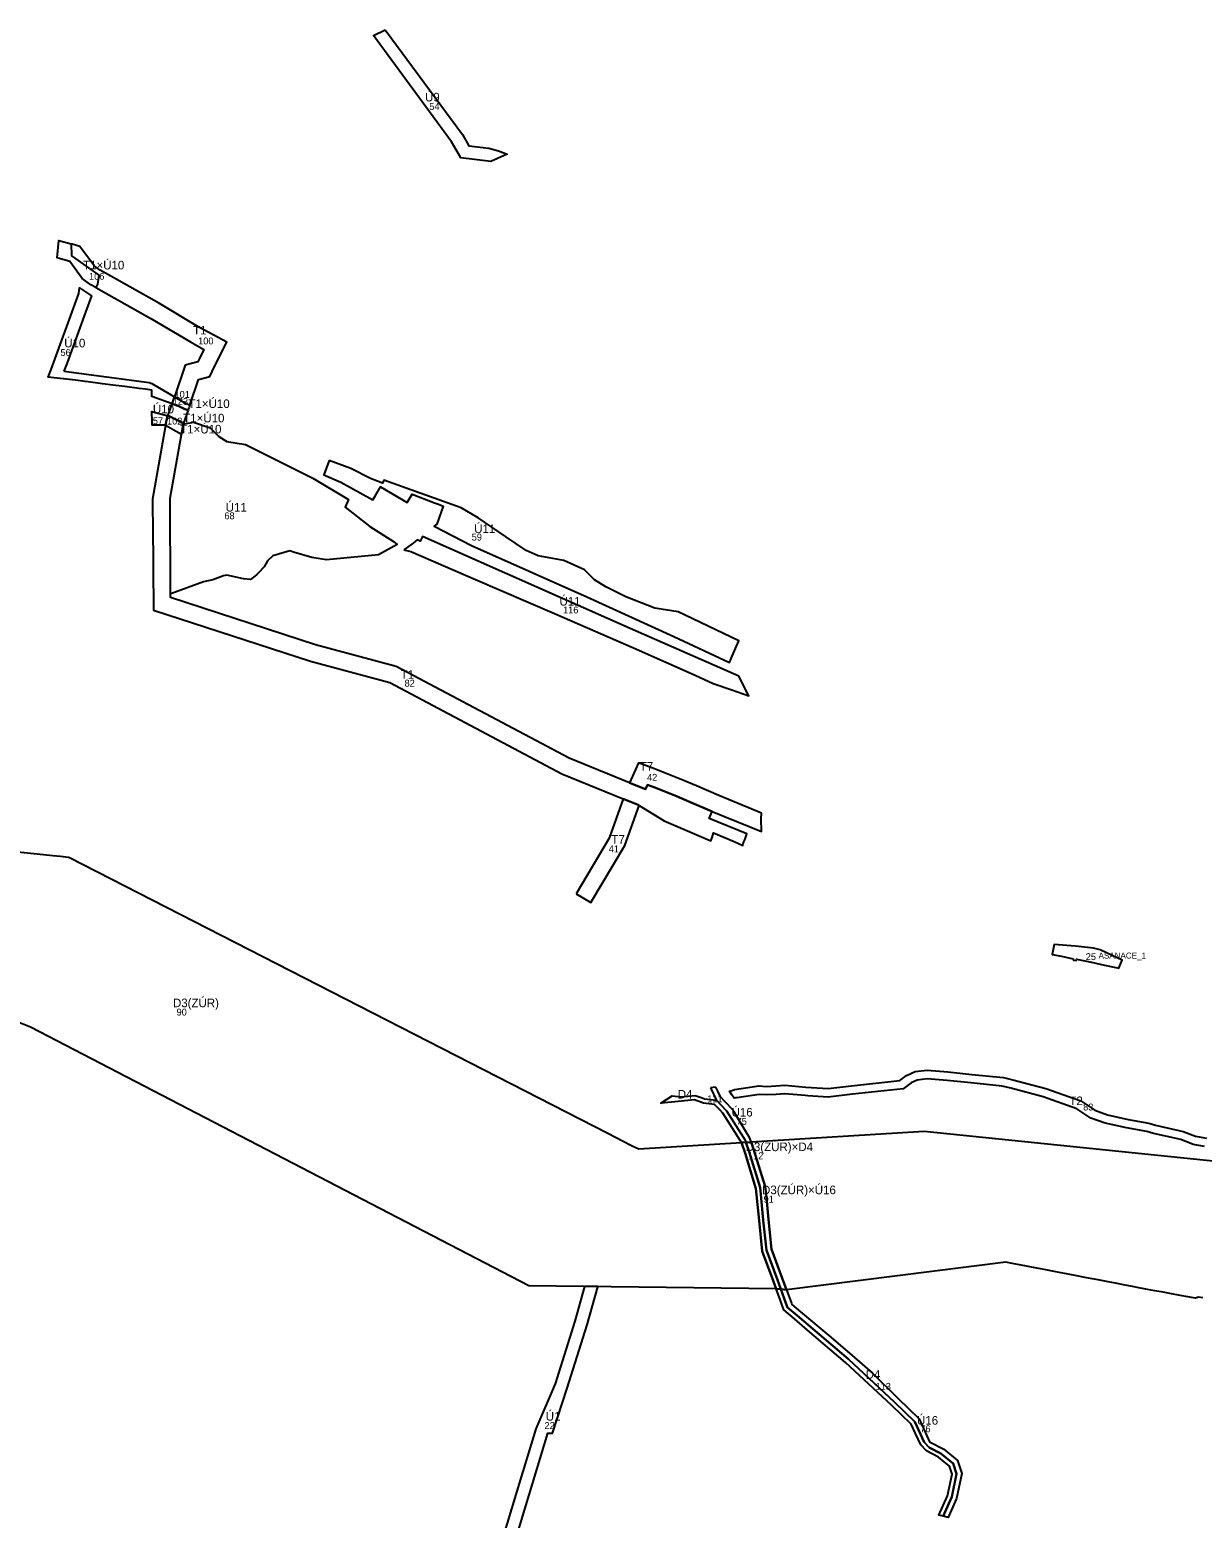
# Model space of a CAD drawing. Extents: x -521621 to -516857, y -1190025 to -1185894.
# Drawn here: x -520831 to -519468, y -1187926 to -1186195 of the extents above; entities that cross this region are included whole.
import ezdxf

# ---------------------------------------------------------------- set-up
doc = ezdxf.new("R2010")
doc.units = 0
for name, color, linetype in [('A_id', 7, 'Continuous'), ('asanace_n', 7, 'Continuous'), ('Implicitní', 7, 'Continuous'), ('VPO_id', 7, 'Continuous'), ('VPO_n', 7, 'Continuous'), ('VPS_id', 7, 'Continuous'), ('VPS_n', 7, 'Continuous')]:
    doc.layers.add(name, color=color, linetype=linetype)

msp = doc.modelspace()

# ---------------------------------------------------------------- linework, layer by layer
at = {"layer": 'Implicitní'}
msp.add_lwpolyline([(-519615.3, -1187260.6), (-519640.1, -1187258.6), (-519642.2, -1187270.1), (-519631.2, -1187272.3), (-519617.7, -1187275.1), (-519617.6, -1187276.6), (-519614.5, -1187277.1), (-519613.9, -1187275.5), (-519596.5, -1187279.2), (-519581.2, -1187282.5), (-519568.1, -1187285.3), (-519564.6, -1187286), (-519560.9, -1187276.9), (-519578.9, -1187268.3), (-519586.4, -1187264.7), (-519594.2, -1187263), (-519615.3, -1187260.6)], dxfattribs=at)
at = {"layer": 'VPO_n'}
for p, q in [((-520033.3, -1187424.5), (-520039.4, -1187425.1)), ((-520033.2, -1187424.5), (-520033.3, -1187424.5))]:
    msp.add_line(p, q, dxfattribs=at)
for points in [[(-520417.7, -1186194.5), (-520328, -1186316.5), (-520320.7, -1186329.4), (-520297.3, -1186332.2), (-520286, -1186335.2), (-520275.9, -1186339.4), (-520295.1, -1186347.6), (-520330, -1186343.4), (-520340.6, -1186324.7), (-520431.4, -1186201.2)], [(-520689, -1186640.8), (-520689, -1186638.6), (-520670.4, -1186643.7), (-520672.1, -1186648.7), (-520673.2, -1186654.8), (-520673.5, -1186654.6), (-520688.9, -1186654.6), (-520688.9, -1186650.8), (-520688.9, -1186646.6), (-520689, -1186642.4)], [(-520602.1, -1186673.3), (-520580.3, -1186677), (-520501.9, -1186716.2), (-520460.6, -1186741.1), (-520464.3, -1186749.8), (-520435.6, -1186772.4), (-520408.2, -1186789.8), (-520404, -1186793.2), (-520425.4, -1186805.4), (-520486.2, -1186811.2), (-520503.1, -1186808.4), (-520524.5, -1186802), (-520528.6, -1186800.8), (-520548.3, -1186806.6), (-520554.7, -1186812.2), (-520558.4, -1186819.3), (-520565.6, -1186826.8), (-520567.5, -1186828.5), (-520570.9, -1186831.2), (-520574.5, -1186833.9), (-520582.6, -1186833.3), (-520601.9, -1186829), (-520605.8, -1186829.6), (-520618.2, -1186834.4), (-520629.1, -1186836.6), (-520667.1, -1186850.8), (-520667.4, -1186850.6), (-520667.8, -1186739.5), (-520654.8, -1186665.4), (-520652.7, -1186653.6), (-520652.2, -1186652.3), (-520650.6, -1186653.1), (-520640.9, -1186650.8), (-520621.4, -1186657.5), (-520611.2, -1186667.5)], [(-519934.8, -1187685.7), (-519901.9, -1187713.3), (-519875.1, -1187736.4), (-519851.3, -1187757), (-519821.2, -1187786.7), (-519796.9, -1187810.2), (-519784.7, -1187837), (-519768.2, -1187845.7), (-519752.4, -1187858.8), (-519747.1, -1187873.8), (-519753.4, -1187903.1), (-519760.9, -1187919.7), (-519763.2, -1187925), (-519769.1, -1187923.5), (-519759.1, -1187901.2), (-519753.3, -1187874.2), (-519757.5, -1187862.4), (-519771.6, -1187850.7), (-519785.2, -1187843.5), (-519790.9, -1187837.6), (-519801.9, -1187813.7), (-519825.4, -1187791.1), (-519879.1, -1187740.9), (-519938.7, -1187690.2), (-519950, -1187680.7), (-519951.9, -1187675.7), (-519957.8, -1187659.5), (-519951.1, -1187660.2), (-519945.5, -1187675.7), (-519944.9, -1187677.2)]]:
    msp.add_lwpolyline(points, close=True, dxfattribs=at)
for points in [[(-520806.4, -1186589.8), (-520774.1, -1186501.4), (-520773.1, -1186494.9), (-520759.2, -1186504.2), (-520766.1, -1186523.1), (-520787.7, -1186581.9), (-520791.3, -1186591.7)], [(-520696.5, -1186612.7), (-520703.8, -1186611.8), (-520720.7, -1186609.6), (-520734.4, -1186607.8), (-520746.6, -1186606.3), (-520763, -1186604.1), (-520766.8, -1186603.7), (-520777.9, -1186602.3), (-520809.6, -1186598.6), (-520806.4, -1186589.8)], [(-520791.3, -1186591.7), (-520692.2, -1186605), (-520689.3, -1186606)], [(-520689.3, -1186606), (-520662.9, -1186621.4), (-520663.4, -1186623.1), (-520664, -1186624.7), (-520664.7, -1186626.7), (-520665.7, -1186629.7), (-520689.1, -1186621.2), (-520689.1, -1186619.3), (-520689.2, -1186617.4), (-520689.2, -1186615.5), (-520689.2, -1186613.7), (-520696.5, -1186612.7)], [(-520483, -1186695.4), (-520489.2, -1186712.1), (-520469.5, -1186720.7), (-520432, -1186741.4), (-520429, -1186736.3), (-520423.1, -1186726.3), (-520392.1, -1186744.3), (-520386.3, -1186734.9), (-520360.4, -1186744.7), (-520355.9, -1186746.4), (-520350.4, -1186748.5), (-520357.9, -1186769.5), (-520360.9, -1186771.9), (-520317.4, -1186794.6), (-520183.2, -1186854.2), (-520082.3, -1186900.2), (-520017.5, -1186930.4), (-520014.4, -1186923.2), (-520006.7, -1186905.2), (-520068.8, -1186875.6), (-520077.1, -1186871.6), (-520104.1, -1186867.2), (-520138.1, -1186854.2), (-520161.4, -1186842.7), (-520174.4, -1186834.4), (-520185.9, -1186822.9), (-520210.1, -1186811.7), (-520240.1, -1186806.4), (-520253.9, -1186800.1), (-520278.1, -1186783.8), (-520309.6, -1186762.1), (-520329.5, -1186750.8), (-520419.4, -1186718.5), (-520421, -1186721.8), (-520434.7, -1186716.6), (-520457.7, -1186705), (-520483, -1186695.4)], [(-520396.3, -1186799.3), (-520387.8, -1186801.4), (-520312.7, -1186834), (-520221, -1186873.7), (-520129.2, -1186913.4), (-520057.4, -1186945.2), (-520036.3, -1186954.9), (-520014.6, -1186962.4), (-519994.8, -1186969.5), (-520006.4, -1186946.6), (-520132.9, -1186890.9), (-520241.6, -1186842.9), (-520374.5, -1186784), (-520377.1, -1186789.5), (-520380.6, -1186787.9), (-520385.2, -1186791.6), (-520396.3, -1186799.3)], [(-520039.4, -1187425.1), (-520038.8, -1187426.7)], [(-520038.8, -1187426.7), (-520032.9, -1187439.3)], [(-520033, -1187425.1), (-520033.2, -1187424.5)], [(-520033, -1187425.1), (-520033, -1187425.1)], [(-520030.7, -1187430), (-520033, -1187425.1)], [(-520032.9, -1187439.3), (-520027.3, -1187445.3)], [(-520027.9, -1187435.9), (-520030.7, -1187430)], [(-520022.9, -1187441.2), (-520027.9, -1187435.9)], [(-520013.3, -1187451.3), (-520022.9, -1187441.2)], [(-520027.3, -1187445.3), (-520020.8, -1187452.1)], [(-520020.8, -1187452.1), (-520004.7, -1187477.6), (-519999.7, -1187485.5)], [(-520012.3, -1187453), (-520013.3, -1187451.3)], [(-519999.7, -1187485.5), (-519999.2, -1187486.2), (-519998.5, -1187488.4), (-519995.4, -1187488.3), (-519992.3, -1187488.1), (-519993.8, -1187483.7), (-520012.3, -1187453)], [(-520273.1, -1187974.4), (-520250.5, -1187898.7), (-520228.5, -1187827.1), (-520223.4, -1187827.1), (-520206.2, -1187774.7), (-520182.9, -1187701.1), (-520170.6, -1187656.6), (-520170.6, -1187656.5), (-520186.1, -1187656.3), (-520197.3, -1187696.8), (-520220.3, -1187769.5), (-520242.6, -1187822), (-520264.9, -1187894.4), (-520287.1, -1187968.9)]]:
    msp.add_lwpolyline(points, dxfattribs=at)
at = {"layer": 'VPS_n'}
for points in [[(-520770, -1186483.8), (-520784.7, -1186463.9), (-520799.1, -1186459.9), (-520797.2, -1186439.6), (-520783, -1186443.6)], [(-520783, -1186443.6), (-520782.5, -1186457.5)], [(-520610.9, -1186575.9), (-520608.8, -1186571.6), (-520601.9, -1186558), (-520611.9, -1186552.6), (-520634.4, -1186540.3), (-520680.3, -1186513), (-520749.2, -1186474.3), (-520755.7, -1186469.5), (-520772.7, -1186446.5), (-520783, -1186443.6), (-520782.5, -1186457.5), (-520774.7, -1186463.1), (-520750.6, -1186480.1), (-520752.2, -1186490.3), (-520754.3, -1186494.4), (-520690.3, -1186530.3), (-520644.3, -1186557.7), (-520638.9, -1186560.6), (-520628.5, -1186566.3), (-520633.9, -1186577.1), (-520635.7, -1186580.7), (-520650.4, -1186584.7), (-520662.9, -1186621.4), (-520655.4, -1186625.8), (-520652.7, -1186627.4), (-520649.5, -1186629.2), (-520647.3, -1186630.2), (-520645.1, -1186631.2), (-520634.9, -1186601.2), (-520621.9, -1186597.7), (-520616.1, -1186586.1), (-520610.9, -1186575.9)], [(-520782.5, -1186457.5), (-520774.7, -1186463.1), (-520750.6, -1186480.1), (-520752.2, -1186490.3), (-520754.3, -1186494.4), (-520760.1, -1186491.2), (-520770, -1186483.8)], [(-520670.4, -1186643.7), (-520665.7, -1186629.7)], [(-520665.7, -1186629.7), (-520657.7, -1186632.5)], [(-520652.2, -1186652.3), (-520669.1, -1186644.1), (-520670.4, -1186643.7)], [(-520657.7, -1186632.5), (-520654.8, -1186633.8)], [(-520654.8, -1186633.8), (-520651.4, -1186635.3)], [(-520647.1, -1186637.2), (-520652.2, -1186652.3)], [(-520651.4, -1186635.3), (-520647.1, -1186637.2)], [(-520001.4, -1187141.2), (-520000.6, -1187139), (-519999.8, -1187136.8), (-519998.6, -1187133.9), (-519998.5, -1187133.4), (-519997.5, -1187130.9), (-519997.3, -1187130.5), (-519997.2, -1187130), (-520041.1, -1187111.9), (-520037.7, -1187103.7), (-520063.8, -1187092.5), (-520079.2, -1187086), (-520104.1, -1187076.1), (-520112.7, -1187072.8), (-520115, -1187077.9), (-520133.6, -1187070.6), (-520203.8, -1187041.8), (-520405, -1186935.1), (-520498.9, -1186909.9), (-520667.4, -1186855), (-520667.4, -1186850.6), (-520667.8, -1186739.5), (-520654.8, -1186665.4), (-520673.2, -1186654.8), (-520688.2, -1186740.5), (-520688, -1186781.6), (-520687.8, -1186807), (-520687.6, -1186824.5), (-520687.6, -1186830.6), (-520687.6, -1186835.5), (-520687.4, -1186853.1), (-520687.3, -1186869.5), (-520504.6, -1186929.1), (-520412.3, -1186953.8), (-520212.4, -1187059.9), (-520140.9, -1187089.3), (-520123.5, -1187096.1), (-520122.4, -1187096.8), (-520093.3, -1187114.7), (-520039.2, -1187137.8), (-520037.7, -1187134.1), (-520036.1, -1187128.8), (-520011.9, -1187138.8), (-520001.8, -1187143.5), (-520001.4, -1187141.2)], [(-520115, -1187077.9), (-520112.7, -1187072.8), (-520104.1, -1187076.1), (-520079.2, -1187086), (-520063.8, -1187092.5), (-520037.7, -1187103.7), (-519980.3, -1187127.3), (-519980.7, -1187112.2), (-519980.3, -1187105.7), (-520030, -1187085.2), (-520056, -1187074.1), (-520071.6, -1187067.5), (-520096.8, -1187057.5), (-520104.8, -1187054.4), (-520123.4, -1187047.1), (-520133.6, -1187070.6), (-520115, -1187077.9)], [(-520195.7, -1187199.5), (-520178.5, -1187209.7), (-520139.1, -1187143.4), (-520122.4, -1187096.8), (-520123.5, -1187096.1), (-520140.9, -1187089.3), (-520157.3, -1187134.8), (-520195.7, -1187199.5)], [(-520849, -1187150.2), (-520815.2, -1187153.9), (-520804.3, -1187155.1), (-520795.3, -1187156), (-520786.2, -1187157), (-520784.9, -1187157.2), (-520159, -1187477.9), (-520132.3, -1187491.8), (-520130, -1187493), (-520122.9, -1187496.1), (-520003.6, -1187488.8), (-519999.4, -1187501.1), (-519986.8, -1187542.4), (-519985.9, -1187549.9), (-519983.1, -1187579.6), (-519979.3, -1187615.3), (-519966.4, -1187650.5), (-519963.3, -1187659), (-520250.8, -1187655.6), (-520830.3, -1187354.9), (-520886.9, -1187332.1)], [(-519465, -1187493.7), (-519478.4, -1187491.1), (-519492.8, -1187485.5), (-519524.5, -1187478.3), (-519532.1, -1187476.1), (-519555.7, -1187471.8), (-519580.6, -1187466.2), (-519597.1, -1187460.4), (-519613.5, -1187449.6), (-519652.6, -1187435.8), (-519690.3, -1187425.6), (-519700.4, -1187423.3), (-519736.7, -1187419.6), (-519764.5, -1187416.6), (-519787.4, -1187414.9), (-519799.1, -1187416.2), (-519806.3, -1187419.4), (-519815.4, -1187426.6), (-519874.4, -1187432.7), (-519902.6, -1187436.1), (-519926.4, -1187434.5), (-519929.4, -1187434.3), (-519953.1, -1187432.2), (-519963, -1187432.9), (-519974.6, -1187433.6), (-519982.9, -1187432.9), (-520009.1, -1187436.9), (-520010.5, -1187437.1), (-520012, -1187437.3), (-520014.8, -1187433.3), (-520017.5, -1187429.2), (-520014.5, -1187428.2), (-520011.5, -1187427.1), (-519983.2, -1187422.8), (-519974.4, -1187423.6), (-519963.6, -1187423), (-519953, -1187422.2), (-519928.6, -1187424.4), (-519902.8, -1187426), (-519875.5, -1187422.8), (-519819.3, -1187416.9), (-519811.5, -1187410.8), (-519801.7, -1187406.4), (-519787.5, -1187404.9), (-519763.6, -1187406.6), (-519735.7, -1187409.7), (-519698.8, -1187413.4), (-519687.9, -1187415.9), (-519649.6, -1187426.2), (-519609, -1187440.6), (-519592.6, -1187451.4), (-519577.8, -1187456.6), (-519553.7, -1187462), (-519529.8, -1187466.3), (-519522, -1187468.6), (-519489.9, -1187475.9), (-519475.7, -1187481.4), (-519462.8, -1187483.9)], [(-520028.4, -1187451.3), (-520034.9, -1187444.5), (-520047.6, -1187443), (-520058.1, -1187439.2), (-520084.9, -1187441.8), (-520097.1, -1187443.1), (-520084.3, -1187434.6), (-520073.6, -1187435.7), (-520057.4, -1187434.1), (-520049.2, -1187437.1), (-520046.4, -1187438.1), (-520032.5, -1187439.7), (-520027.3, -1187445.3), (-520020.8, -1187452.1)], [(-520003.6, -1187488.8), (-520003.8, -1187488.4), (-520008.9, -1187480.3), (-520025, -1187454.8), (-520028.4, -1187451.3)], [(-520020.8, -1187452.1), (-520004.7, -1187477.6), (-519999.7, -1187485.5), (-519999.2, -1187486.2), (-519998.5, -1187488.4), (-520003.6, -1187488.8)], [(-519467.2, -1187669.7), (-519472.1, -1187668.6), (-519475.5, -1187670.1), (-519486.8, -1187668), (-519495.4, -1187666.4), (-519503.6, -1187664.9), (-519513.2, -1187663.1), (-519522.7, -1187661.3), (-519531.3, -1187659.7), (-519535.2, -1187659), (-519541.3, -1187657.8), (-519548.9, -1187656.4), (-519559.1, -1187654.4), (-519568.5, -1187652.6), (-519577.2, -1187651), (-519587, -1187649.1), (-519592.9, -1187647.9), (-519595.9, -1187647.4), (-519604.1, -1187645.8), (-519613.4, -1187644), (-519623.8, -1187642), (-519636, -1187639.7), (-519642, -1187638.6), (-519651.6, -1187636.7), (-519660.2, -1187635.1), (-519670.3, -1187633.1), (-519680.2, -1187631.2), (-519688.7, -1187629.6), (-519696.3, -1187628.1), (-519951.1, -1187660.2), (-519956.1, -1187646.7), (-519968.5, -1187612.8), (-519972.2, -1187578.6), (-519974.9, -1187548.7), (-519976, -1187540.1), (-519989, -1187497.8), (-519992.3, -1187488.1), (-519790.9, -1187475.7), (-519421.5, -1187513.5)], [(-520003.6, -1187488.8), (-519998.5, -1187488.4)], [(-519998.5, -1187488.4), (-519994.7, -1187499.6), (-519981.9, -1187541.3), (-519980.9, -1187549.3), (-519978.1, -1187579.2), (-519974.4, -1187614.2), (-519961.7, -1187648.8), (-519957.8, -1187659.5), (-519963.3, -1187659), (-519966.4, -1187650.5), (-519979.3, -1187615.3), (-519983.1, -1187579.6), (-519985.9, -1187549.9), (-519986.8, -1187542.4), (-519999.4, -1187501.1), (-520003.6, -1187488.8)]]:
    msp.add_lwpolyline(points, dxfattribs=at)
for points in [[(-520665.7, -1186629.7), (-520662.9, -1186621.4), (-520655.4, -1186625.8), (-520652.7, -1186627.4), (-520649.5, -1186629.2), (-520647.3, -1186630.2), (-520645.1, -1186631.2), (-520645.5, -1186632.5), (-520645.9, -1186633.8), (-520646.5, -1186635.5), (-520647.1, -1186637.2), (-520651.4, -1186635.3), (-520654.8, -1186633.8), (-520657.7, -1186632.5)], [(-520670.4, -1186643.7), (-520669.1, -1186644.1), (-520652.2, -1186652.3), (-520652.7, -1186653.6), (-520654.8, -1186665.4), (-520673.2, -1186654.8), (-520672.1, -1186648.7)], [(-519992.3, -1187488.1), (-519989, -1187497.8), (-519976, -1187540.1), (-519974.9, -1187548.7), (-519972.2, -1187578.6), (-519968.5, -1187612.8), (-519956.1, -1187646.7), (-519951.1, -1187660.2), (-519957.8, -1187659.5), (-519961.7, -1187648.8), (-519974.4, -1187614.2), (-519978.1, -1187579.2), (-519980.9, -1187549.3), (-519981.9, -1187541.3), (-519994.7, -1187499.6), (-519998.5, -1187488.4)], [(-519957.8, -1187659.5), (-519951.9, -1187675.7), (-519950, -1187680.7), (-519938.7, -1187690.2), (-519879.1, -1187740.9), (-519825.4, -1187791.1), (-519801.9, -1187813.7), (-519790.9, -1187837.6), (-519785.2, -1187843.5), (-519771.6, -1187850.7), (-519757.5, -1187862.4), (-519753.3, -1187874.2), (-519759.1, -1187901.2), (-519769.1, -1187923.5), (-519774, -1187922.2), (-519763.9, -1187899.7), (-519758.5, -1187874.5), (-519761.7, -1187865.3), (-519772, -1187856.8), (-519774.4, -1187854.9), (-519788.2, -1187847.5), (-519795.1, -1187840.5), (-519801.2, -1187827.2), (-519806.1, -1187816.7), (-519828.8, -1187794.7), (-519882.4, -1187744.6), (-519926.7, -1187707), (-519941.9, -1187694.1), (-519954.2, -1187683.7), (-519956.5, -1187677.4), (-519958.3, -1187672.7), (-519963.3, -1187659)]]:
    msp.add_lwpolyline(points, close=True, dxfattribs=at)

# ---------------------------------------------------------------- texts
at = {"layer": 'A_id'}
msp.add_text('25', height=8, dxfattribs=at).set_placement((-519603.2, -1187276.7))
at = {"layer": 'asanace_n'}
msp.add_text('ASANACE_1', height=7, dxfattribs=at).set_placement((-519588.3, -1187274.9))
at = {"layer": 'VPO_id'}
for s, p in [('54', (-520366.5, -1186287.8)), ('56', (-520795.4, -1186574)), ('57', (-520688, -1186653.3)), ('68', (-520604.8, -1186763.9)), ('59', (-520317.2, -1186788.7)), ('116', (-520211, -1186873.4)), ('75', (-520009.2, -1187468.3)), ('22', (-520232.5, -1187822.1)), ('76', (-519795.6, -1187825.9))]:
    msp.add_text(s, height=8, dxfattribs=at).set_placement(p)
at = {"layer": 'VPO_n'}
for s, p in [('Ú9', (-520371.5, -1186277.9)), ('Ú10', (-520791, -1186564)), ('Ú10', (-520687.9, -1186640.7)), ('Ú11', (-520603.3, -1186755)), ('Ú11', (-520314.3, -1186780)), ('Ú11', (-520215.1, -1186864.3)), ('Ú16', (-520015, -1187458.7)), ('Ú1', (-520231.1, -1187812.4)), ('Ú16', (-519799.4, -1187817.1))]:
    msp.add_text(s, height=10, dxfattribs=at).set_placement(p)
at = {"layer": 'VPS_id'}
for s, p in [('106', (-520762.2, -1186485.3)), ('100', (-520635.3, -1186560.5)), ('123', (-520664.9, -1186630.8)), ('101', (-520662.8, -1186622.7)), ('102', (-520671.5, -1186653.7)), ('82', (-520395.3, -1186958.6)), ('42', (-520113.3, -1187068.1)), ('41', (-520157.9, -1187151.4)), ('90', (-520660.4, -1187341.2)), ('111', (-520043.3, -1187442.1)), ('83', (-519606.2, -1187451.6)), ('112', (-519996, -1187508.4)), ('91', (-519977.8, -1187558.9)), ('113', (-519847.6, -1187776.5))]:
    msp.add_text(s, height=8, dxfattribs=at).set_placement(p)
at = {"layer": 'VPS_n'}
for s, p in [('T1×Ú10', (-520769.1, -1186473.3)), ('T1', (-520641.1, -1186549)), ('T1×Ú10', (-520646.6, -1186634.5)), ('T1×Ú10', (-520652.7, -1186651.2)), ('T1×Ú10', (-520656.2, -1186664.1)), ('T1', (-520399.8, -1186949.5)), ('T7', (-520121.8, -1187056.4)), ('T7', (-520154.8, -1187141.3)), ('D3(ZÚR)', (-520664.6, -1187331.5)), ('D4', (-520077.6, -1187437.7)), ('T2', (-519622.2, -1187445.4)), ('D3(ZÚR)×D4', (-519998.7, -1187498.9)), ('D3(ZÚR)×Ú16', (-519979.6, -1187549)), ('D4', (-519859.2, -1187763.8))]:
    msp.add_text(s, height=10, dxfattribs=at).set_placement(p)

doc.saveas('drawing.dxf')
